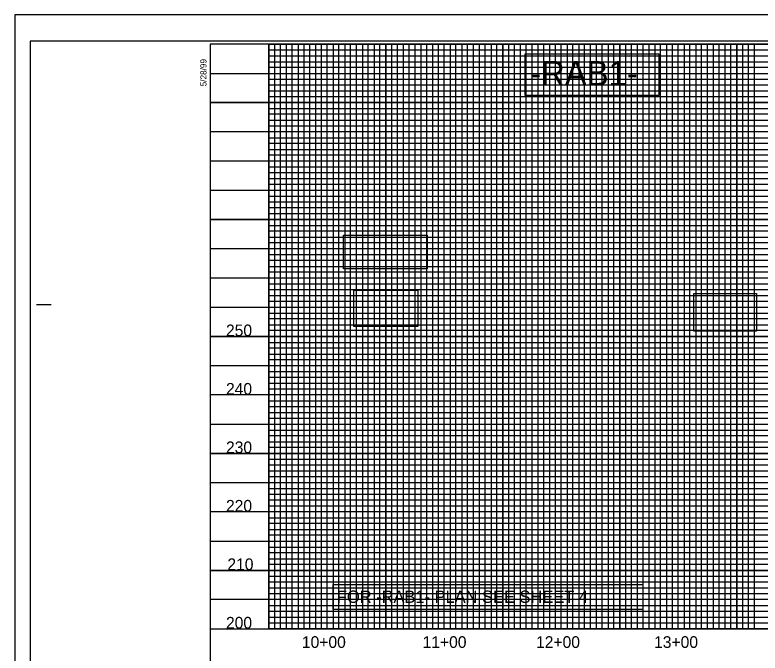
# Model space of a CAD drawing. Extents: x 1810963 to 1812934, y 722070 to 723170.
# Drawn here: x 1810963 to 1811600, y 722624 to 723170 of the extents above; entities that cross this region are included whole.
import ezdxf

# ---------------------------------------------------------------- set-up
doc = ezdxf.new("R2010")
doc.units = 0
for name, color, linetype in [('Exist Horizontal Alignment Tick Label', 7, 'Continuous'), ('Old_Level_11', 7, 'Continuous'), ('Old_Level_2', 7, 'Continuous'), ('Prop Conc 2ft 6in Curb and Gutter', 7, 'Continuous'), ('Prop RDY Traffic Signal CELL', 7, 'Continuous'), ('Prop Shade Heavy', 7, 'Continuous'), ('Prop Shade Light', 7, 'Continuous'), ('Scratch_Level_0', 7, 'Continuous'), ('Scratch_Level_3', 7, 'Continuous'), ('Scratch_Level_5', 7, 'Continuous'), ('Sheet Block Title CELL', 7, 'Continuous'), ('Sheet North Arrow CELL', 7, 'Continuous'), ('Sheet Symbology CELL', 7, 'Continuous'), ('Sheet Title CELL', 7, 'Continuous')]:
    doc.layers.add(name, color=color, linetype=linetype)

msp = doc.modelspace()

# ---------------------------------------------------------------- linework, layer by layer
at = {"layer": 'Old_Level_11'}
msp.add_lwpolyline([(1810976.46, 722092.33), (1812642.96, 722092.33), (1812642.96, 723147.43), (1810976.46, 723147.43)], close=True, dxfattribs=at)
at = {"layer": 'Old_Level_2'}
for points in [[(1811399.67, 723136.45), (1811513.83, 723136.45), (1811513.83, 723101.06), (1811399.67, 723101.06)], [(1811244.33, 722981.59), (1811315.95, 722981.59), (1811315.95, 722952.71), (1811244.33, 722952.71)], [(1811253.3, 722934.57), (1811307.95, 722934.57), (1811307.95, 722903.44), (1811253.3, 722903.44)], [(1811543.71, 722931.68), (1811597.48, 722931.68), (1811597.48, 722899.5), (1811543.71, 722899.5)], [(1811235.5, 722682.94), (1811500.18, 722682.94), (1811500.18, 722661.42), (1811235.5, 722661.42)]]:
    msp.add_lwpolyline(points, close=True, dxfattribs=at)
at = {"layer": 'Prop Conc 2ft 6in Curb and Gutter'}
for p, q in [((1811180.46, 722644.88), (1811180.46, 723144.88)), ((1811230.46, 722644.88), (1811230.46, 723144.88)), ((1811280.46, 722644.88), (1811280.46, 723144.88)), ((1811330.46, 722644.88), (1811330.46, 723144.88)), ((1811380.46, 722644.88), (1811380.46, 723144.88)), ((1811430.46, 722644.88), (1811430.46, 723144.88)), ((1811480.46, 722644.88), (1811480.46, 723144.88)), ((1811530.46, 722644.88), (1811530.46, 723144.88)), ((1811580.46, 722644.88), (1811580.46, 723144.88)), ((1812230.42, 723094.88), (1811130.46, 723094.88)), ((1812430.41, 723044.88), (1811130.46, 723044.88)), ((1812430.46, 722994.88), (1811130.46, 722994.88)), ((1812630.46, 722944.88), (1811130.46, 722944.88)), ((1812630.46, 722894.88), (1811130.46, 722894.88)), ((1812630.46, 722844.88), (1811130.46, 722844.88)), ((1812630.46, 722794.88), (1811130.46, 722794.88)), ((1812630.46, 722744.88), (1811130.46, 722744.88)), ((1812630.46, 722694.88), (1811130.46, 722694.88))]:
    msp.add_line(p, q, dxfattribs=at)
at = {"layer": 'Prop RDY Traffic Signal CELL'}
for p, q in [((1812647.46, 723169.88), (1810963.46, 723169.88)), ((1810963.46, 723169.88), (1810963.46, 722069.88))]:
    msp.add_line(p, q, dxfattribs=at)
at = {"layer": 'Prop Shade Heavy'}
for points in [[(1811180.46, 723144.88), (1811180.46, 722644.88), (1811230.46, 722644.88), (1811230.46, 723144.88), (1811280.46, 723144.88), (1811280.46, 722644.88), (1811330.46, 722644.88), (1811330.46, 723144.88), (1811380.46, 723144.88), (1811380.46, 722644.88), (1811430.46, 722644.88), (1811430.46, 723144.88), (1811480.46, 723144.88), (1811480.46, 722644.88), (1811530.46, 722644.88), (1811530.46, 723144.88), (1811580.46, 723144.88), (1811580.46, 722644.88), (1811630.46, 722644.88)], [(1811130.46, 723094.88), (1812230.42, 723094.88)], [(1812430.46, 723044.88), (1811130.46, 723044.88), (1811130.46, 722994.88), (1812430.46, 722994.88)], [(1812630.46, 722944.88), (1811130.46, 722944.88), (1811130.46, 722894.88), (1812630.46, 722894.88)], [(1812630.46, 722844.88), (1811130.46, 722844.88), (1811130.46, 722794.88), (1812630.46, 722794.88)], [(1812630.46, 722744.88), (1811130.46, 722744.88), (1811130.46, 722744.88), (1811130.46, 722694.88), (1812630.46, 722694.88)]]:
    msp.add_lwpolyline(points, dxfattribs=at)
at = {"layer": 'Prop Shade Light'}
for p, q in [((1811205.46, 723144.88), (1811205.46, 722644.88)), ((1811255.46, 722644.88), (1811255.46, 723144.88)), ((1811255.46, 723144.88), (1811305.46, 723144.88)), ((1811305.46, 723144.88), (1811305.46, 722644.88)), ((1811355.46, 722644.88), (1811355.46, 723144.88)), ((1811355.46, 723144.88), (1811405.46, 723144.88)), ((1811405.46, 723144.88), (1811405.46, 722644.88)), ((1811455.46, 722644.88), (1811455.46, 723144.88)), ((1811455.46, 723144.88), (1811505.46, 723144.88)), ((1811505.46, 723144.88), (1811505.46, 722644.88)), ((1811555.46, 722644.88), (1811555.46, 723144.88)), ((1811555.46, 723144.88), (1811605.46, 723144.88)), ((1811130.46, 723119.88), (1812230.42, 723119.88)), ((1811205.46, 722644.88), (1811255.46, 722644.88)), ((1811305.46, 722644.88), (1811355.46, 722644.88)), ((1811405.46, 722644.88), (1811455.46, 722644.88)), ((1811505.46, 722644.88), (1811555.46, 722644.88))]:
    msp.add_line(p, q, dxfattribs=at)
for points in [[(1812430.46, 723069.88), (1811130.46, 723069.88), (1811130.46, 723019.88), (1812430.46, 723019.88)], [(1812630.46, 722969.88), (1811130.46, 722969.88), (1811130.46, 722919.88), (1812455.46, 722919.88)], [(1812630.46, 722869.88), (1811130.46, 722869.88), (1811130.46, 722819.88), (1812630.46, 722819.88)], [(1812630.46, 722769.88), (1811130.46, 722769.88), (1811130.46, 722719.88), (1812630.46, 722719.88)], [(1812630.46, 722669.88), (1811130.46, 722669.88)]]:
    msp.add_lwpolyline(points, dxfattribs=at)
at = {"layer": 'Scratch_Level_3'}
msp.add_lwpolyline([(1811180.46, 723144.88), (1812230.46, 723144.88), (1812230.46, 723092.45), (1812430.5, 723092.45), (1812430.41, 722983.83), (1812580.46, 722983.83), (1812580.46, 722644.88), (1811180.46, 722644.88)], close=True, dxfattribs=at)
at = {"layer": 'Scratch_Level_5'}
msp.add_lwpolyline([(1811180.46, 722983.83), (1811180.46, 722644.88), (1812580.46, 722644.88), (1812580.46, 722983.83)], dxfattribs=at)
at = {"layer": 'Sheet North Arrow CELL'}
msp.add_lwpolyline([(1810963.46, 722069.88), (1812647.46, 722069.88), (1812647.46, 723169.88), (1810963.46, 723169.88)], close=True, dxfattribs=at)
at = {"layer": 'Sheet Symbology CELL'}
for p, q in [((1810981.96, 722922.38), (1810994.46, 722922.38)), ((1811130.46, 722644.88), (1812630.46, 722644.88))]:
    msp.add_line(p, q, dxfattribs=at)
msp.add_lwpolyline([(1812630.46, 723144.88), (1811130.46, 723144.88), (1811130.46, 722094.88), (1812630.46, 722094.88)], close=True, dxfattribs=at)
at = {"layer": 'Sheet Title CELL'}
for p, q in [((1811180.46, 723139.88), (1812230.42, 723139.88)), ((1811180.46, 723134.88), (1811180.46, 723134.88)), ((1812230.42, 723134.82), (1811180.46, 723134.53)), ((1811180.46, 723129.88), (1812230.42, 723129.88)), ((1812230.42, 723099.88), (1811180.46, 723099.88)), ((1811180.46, 723099.88), (1811180.46, 723089.88)), ((1811180.46, 723089.88), (1812430.46, 723089.88)), ((1812430.41, 723009.88), (1811180.46, 723009.88)), ((1812430.46, 723004.88), (1811180.46, 723004.88)), ((1812430.46, 722999.88), (1811180.46, 722999.88)), ((1811180.46, 722989.88), (1812430.46, 722989.88)), ((1812430.46, 722984.88), (1811180.46, 722984.88)), ((1811180.46, 722979.88), (1812580.46, 722979.88)), ((1812580.46, 722959.88), (1811180.46, 722959.88)), ((1811180.46, 722954.88), (1812580.46, 722954.88)), ((1812580.46, 722934.88), (1811180.46, 722934.88)), ((1811180.46, 722929.88), (1812580.46, 722929.88)), ((1812580.46, 722909.88), (1811180.46, 722909.88)), ((1811180.46, 722904.88), (1812580.46, 722904.88)), ((1812580.46, 722899.88), (1811180.46, 722899.88)), ((1811180.46, 722889.88), (1812580.46, 722889.88)), ((1812580.46, 722884.88), (1811180.46, 722884.88)), ((1811180.46, 722879.88), (1812580.46, 722879.88)), ((1812580.46, 722874.88), (1811180.46, 722874.88)), ((1811180.46, 722864.88), (1812580.46, 722864.88)), ((1812580.46, 722859.88), (1811180.46, 722859.88)), ((1811180.46, 722854.88), (1812580.46, 722854.88)), ((1812580.46, 722849.88), (1811180.46, 722849.88)), ((1811180.46, 722839.88), (1812580.46, 722839.88)), ((1812580.46, 722834.88), (1811180.46, 722834.88)), ((1811180.46, 722829.88), (1812580.46, 722829.88)), ((1812580.46, 722824.88), (1811180.46, 722824.88)), ((1811180.46, 722814.88), (1812580.46, 722814.88)), ((1812580.46, 722809.88), (1811180.46, 722809.88)), ((1811180.46, 722804.88), (1812580.46, 722804.88)), ((1812580.46, 722799.88), (1811180.46, 722799.88)), ((1811180.46, 722789.88), (1812580.46, 722789.88)), ((1812580.46, 722784.88), (1811180.46, 722784.88)), ((1811180.46, 722779.88), (1812580.46, 722779.88)), ((1812580.46, 722774.88), (1811180.46, 722774.88)), ((1811180.46, 722764.88), (1812580.46, 722764.88)), ((1812580.46, 722759.88), (1811180.46, 722759.88)), ((1812580.46, 722754.88), (1811180.46, 722754.88)), ((1812580.46, 722749.88), (1811180.46, 722749.88)), ((1811180.46, 722739.88), (1812580.46, 722739.88)), ((1812580.46, 722734.88), (1811180.46, 722734.88)), ((1811180.46, 722729.88), (1812580.46, 722729.88)), ((1812580.46, 722724.88), (1811180.46, 722724.88)), ((1811180.46, 722714.88), (1812580.46, 722714.88)), ((1812580.46, 722709.88), (1811180.46, 722709.88)), ((1811180.46, 722704.88), (1812580.46, 722704.88)), ((1812580.46, 722699.88), (1811180.46, 722699.88)), ((1811180.46, 722689.88), (1812580.46, 722689.88)), ((1812580.46, 722684.88), (1811180.46, 722684.88)), ((1811180.46, 722679.88), (1812580.46, 722679.88)), ((1812580.46, 722674.88), (1811180.46, 722674.88)), ((1811180.46, 722664.88), (1812580.46, 722664.88)), ((1812580.46, 722659.88), (1811180.46, 722659.88)), ((1811180.46, 722654.88), (1812580.46, 722654.88))]:
    msp.add_line(p, q, dxfattribs=at)
for points in [[(1811185.46, 723144.88), (1811185.46, 722644.88), (1811190.46, 722644.88), (1811190.46, 723144.88), (1811195.46, 723144.88), (1811195.46, 722644.88), (1811200.46, 722644.88), (1811200.46, 723144.88), (1811210.46, 723144.88), (1811210.46, 722644.88), (1811215.46, 722644.88), (1811215.46, 723144.88), (1811220.46, 723144.88), (1811220.46, 722644.88), (1811225.46, 722644.88), (1811235.46, 722644.88), (1811240.46, 722644.88), (1811240.46, 723144.88), (1811245.46, 723144.88), (1811245.46, 722644.88), (1811250.46, 722644.88), (1811250.46, 723144.88), (1811260.46, 723144.88), (1811260.46, 722644.88), (1811265.46, 722644.88), (1811265.46, 723144.88), (1811270.46, 723144.88), (1811270.46, 722644.88), (1811275.46, 722644.88), (1811275.46, 723144.88), (1811285.46, 723144.88), (1811285.46, 722644.88), (1811290.46, 722644.88), (1811290.46, 723144.88), (1811295.46, 723144.88), (1811295.46, 722644.88), (1811300.46, 722644.88), (1811300.46, 723144.88), (1811310.46, 723144.88), (1811310.46, 722644.88), (1811315.46, 722644.88), (1811315.46, 723144.88), (1811320.46, 723144.88), (1811320.46, 722644.88), (1811325.46, 722644.88), (1811325.46, 723144.88), (1811335.46, 723144.88), (1811335.46, 722644.88), (1811340.46, 722644.88), (1811340.46, 723144.88), (1811345.46, 723144.88), (1811345.46, 722644.88), (1811350.46, 722644.88), (1811350.46, 723144.88), (1811360.46, 723144.88), (1811360.46, 722644.88), (1811365.46, 722644.88), (1811365.46, 723144.88), (1811370.46, 723144.88), (1811370.46, 722644.88), (1811375.46, 722644.88), (1811375.46, 723144.88), (1811385.46, 723144.88), (1811385.46, 722644.88), (1811390.46, 722644.88), (1811390.46, 723144.88), (1811395.46, 723144.88), (1811395.46, 722644.88)], [(1811225.46, 722644.88), (1811225.46, 723144.88), (1811235.46, 723144.88), (1811235.46, 722644.88)], [(1811395.46, 722644.88), (1811400.46, 722644.88), (1811400.46, 723144.88), (1811410.46, 723144.88), (1811410.46, 722644.88), (1811415.46, 722644.88), (1811415.46, 723144.88), (1811420.46, 723144.88), (1811420.46, 722644.88), (1811425.46, 722644.88), (1811425.46, 723144.88), (1811435.46, 723144.88), (1811435.46, 722644.88), (1811440.46, 722644.88), (1811440.46, 723144.88), (1811445.46, 723144.88), (1811445.46, 722644.88), (1811450.46, 722644.88), (1811450.46, 723144.88), (1811460.46, 723144.88), (1811460.46, 722644.88), (1811465.46, 722644.88), (1811465.46, 723144.88), (1811470.46, 723144.88), (1811470.46, 722644.88), (1811475.46, 722644.88), (1811475.46, 723144.88), (1811485.46, 723144.88), (1811485.46, 722644.88), (1811490.46, 722644.88), (1811490.46, 723144.88), (1811495.46, 723144.88), (1811495.46, 722644.88), (1811500.46, 722644.88), (1811500.46, 723144.88), (1811510.46, 723144.88), (1811510.46, 722644.88), (1811515.46, 722644.88), (1811515.46, 723144.88), (1811520.46, 723144.88), (1811520.46, 722644.88), (1811525.46, 722644.88), (1811525.46, 723144.88), (1811535.46, 723144.88), (1811535.46, 722644.88), (1811540.46, 722644.88), (1811540.46, 723144.88), (1811545.46, 723144.88), (1811545.46, 722644.88), (1811550.46, 722644.88), (1811550.46, 723144.88), (1811560.46, 723144.88), (1811560.46, 722644.88), (1811565.46, 722644.88), (1811565.46, 723144.88), (1811570.46, 723144.88), (1811570.46, 722644.88), (1811575.46, 722644.88), (1811575.46, 723144.88), (1811585.46, 723144.88), (1811585.46, 722644.88), (1811590.46, 722644.88), (1811590.46, 723144.88), (1811595.46, 723144.88), (1811595.46, 722644.88), (1811600.46, 722644.88)], [(1812230.42, 723124.88), (1811180.46, 723124.88), (1811180.46, 723114.88), (1812230.42, 723114.88)], [(1812230.42, 723109.88), (1811180.46, 723109.88), (1811180.46, 723104.88), (1812230.42, 723104.88)], [(1812430.46, 723084.88), (1811180.46, 723084.88), (1811180.46, 723079.88), (1812430.46, 723079.88)], [(1812430.46, 723074.88), (1811180.46, 723074.88), (1811180.46, 723064.88), (1812430.46, 723064.88)], [(1812430.46, 723059.88), (1811180.46, 723059.88), (1811180.46, 723054.88), (1812430.46, 723054.88)], [(1812430.46, 723049.88), (1811180.46, 723049.88), (1811180.46, 723039.88), (1812430.46, 723039.88)], [(1812430.46, 723034.78), (1811180.56, 723034.78), (1811180.56, 723029.88), (1812430.46, 723029.88)], [(1812430.46, 723024.88), (1811180.46, 723024.88), (1811180.46, 723014.88), (1812430.46, 723014.88)], [(1812580.46, 722974.88), (1811180.46, 722974.88), (1811180.46, 722964.88), (1812580.46, 722964.88)], [(1812580.46, 722949.88), (1811180.46, 722949.88), (1811180.46, 722939.88), (1812580.46, 722939.88)], [(1812580.46, 722924.88), (1811180.46, 722924.88), (1811180.46, 722914.88), (1812580.46, 722914.88)], [(1812580.46, 722649.88), (1811180.46, 722649.88)]]:
    msp.add_lwpolyline(points, dxfattribs=at)

# ---------------------------------------------------------------- texts
at = {"layer": 'Exist Horizontal Alignment Tick Label'}
for s, height, p in [('-RAB1-', 21, (1811403.87, 723109.49)), ('FOR -RAB1- PLAN SEE SHEET 4', 10.5, (1811238.74, 722667.13))]:
    msp.add_text(s, height=height, rotation=360, dxfattribs=at).set_placement(p)
at = {"layer": 'Scratch_Level_0'}
for s, p in [('250', (1811143.89, 722895.13)), ('240', (1811143.89, 722845.13)), ('230', (1811143.89, 722795.13)), ('220', (1811143.89, 722745.13)), ('210', (1811145.09, 722695.13)), ('200', (1811143.89, 722645.13))]:
    msp.add_text(s, height=10, dxfattribs=at).set_placement(p)
at = {"layer": 'Sheet Block Title CELL'}
for s, p in [('10+00', (1811208.78, 722628.6)), ('11+00', (1811311.94, 722628.6)), ('12+00', (1811408.92, 722628.6)), ('13+00', (1811509.84, 722628.6))]:
    msp.add_text(s, height=10, dxfattribs=at).set_placement(p)
at = {"layer": 'Sheet Symbology CELL'}
msp.add_text('5/28/99', height=5.25, rotation=90, dxfattribs=at).set_placement((1811127.22, 723108.79))

doc.saveas('drawing.dxf')
